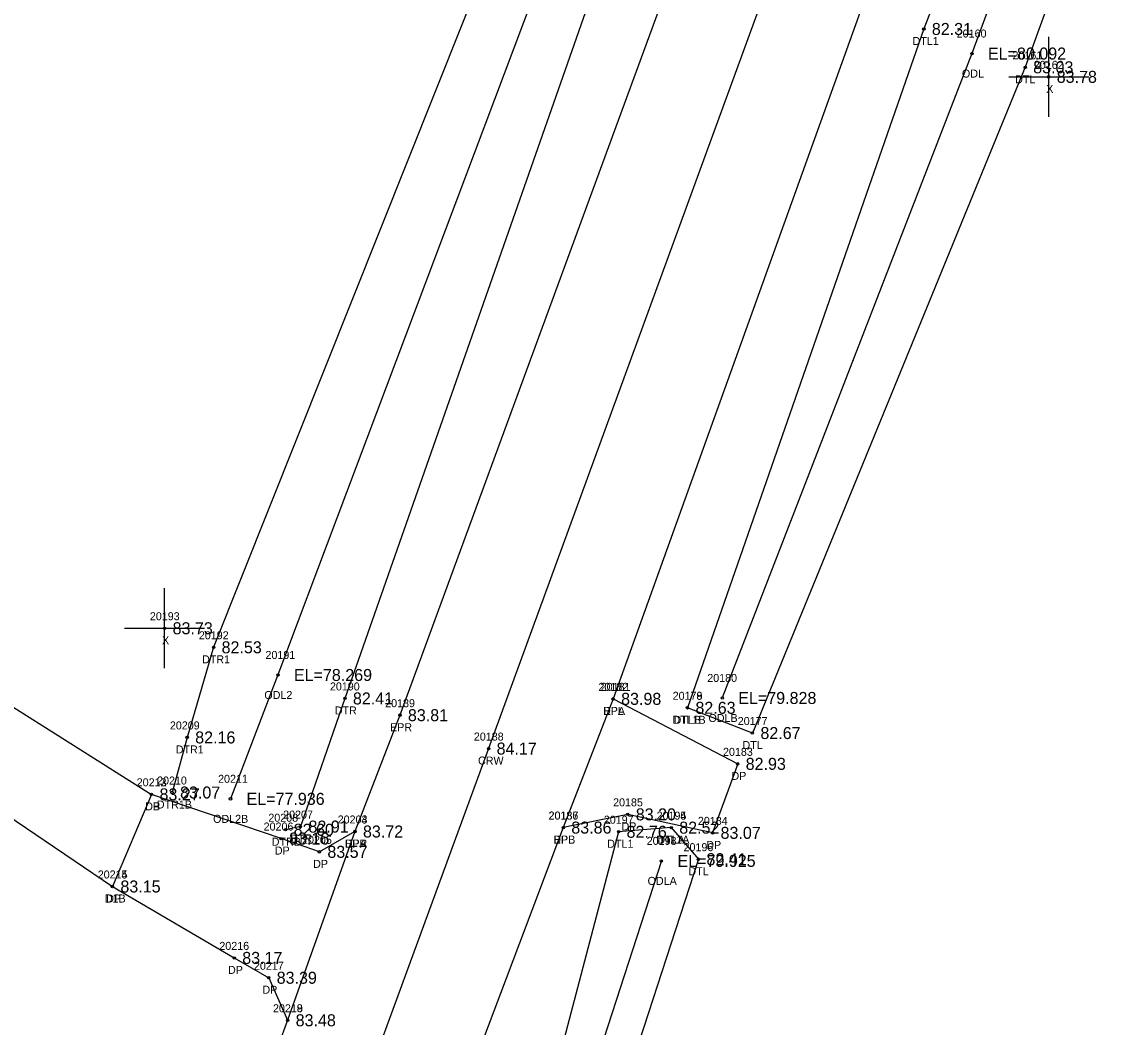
# Model space of a CAD drawing. Extents: x 2140110 to 2141565, y 506241 to 510327.
# Drawn here: x 2141166.2 to 2141303, y 509748.5 to 509874.1 of the extents above; entities that cross this region are included whole.
import ezdxf

# ---------------------------------------------------------------- set-up
doc = ezdxf.new("R2010")
doc.units = 0
for name, color, linetype in [('RD_DTM_BkLn1', 7, 'Continuous'), ('RD_EX_Driveway', 7, 'Continuous'), ('RD_EX_Driveway_txCode', 7, 'Continuous'), ('RD_EX_H2O', 7, 'Continuous'), ('RD_EX_H2O_txCode', 7, 'Continuous'), ('RD_EX_Misc', 7, 'Continuous'), ('RD_EX_Misc_txCode', 7, 'Continuous'), ('RD_EX_Road', 7, 'Continuous'), ('RD_EX_Road_txCode', 7, 'Continuous'), ('RD_EX_TX_Driveway_ELEV', 7, 'Continuous'), ('RD_EX_TX_H2O_ELEV', 7, 'Continuous'), ('RD_EX_TX_Misc_ELEV', 7, 'Continuous'), ('RD_EX_TX_Road_ELEV', 7, 'Continuous'), ('RD_HC_Survey_ELEV', 7, 'Continuous'), ('RD_HC_Survey_txCode', 7, 'Continuous'), ('RD_SMD_Locator', 7, 'Continuous')]:
    doc.layers.add(name, color=color, linetype=linetype)

msp = doc.modelspace()

# ---------------------------------------------------------------- linework, layer by layer
at = {"layer": 'RD_DTM_BkLn1'}
msp.add_lwpolyline([(2141401.24, 510292.17), (2141386.62, 510241.55), (2141370.29, 510189.18), (2141352.34, 510135.64), (2141334.07, 510083.82), (2141314.82, 510031.25), (2141297.4, 509983.45), (2141260.01, 509880.66), (2141224.45, 509783.3), (2141187.1, 509681.41), (2141150.45, 509581.24), (2141112.96, 509478.26), (2141074.89, 509374.78), (2141038.89, 509276.46), (2141003.79, 509180.59), (2140969.89, 509087.8), (2140962.46, 509066.85), (2140921.91, 508956.12), (2140885.66, 508857.72), (2140850.55, 508762.05)], dxfattribs=at)
at = {"layer": 'RD_EX_Driveway'}
for p, q in [((2141078.27, 509843.32), (2141182.34, 509777.58)), ((2141073.6, 509836.63), (2141177.46, 509766.07))]:
    msp.add_line(p, q, dxfattribs=at)
for points in [[(2141240, 509789.51), (2141255.56, 509781.39), (2141252.42, 509772.77), (2141241.83, 509775.08), (2141233.78, 509773.43)], [(2141207.76, 509772.94), (2141203.31, 509770.4), (2141198.53, 509772.06), (2141182.34, 509777.58), (2141177.46, 509766.07), (2141192.68, 509757.15), (2141196.98, 509754.67), (2141199.35, 509749.36)]]:
    msp.add_lwpolyline(points, dxfattribs=at)
at = {"layer": 'RD_EX_H2O'}
msp.add_line((2141246.04, 509769.27), (2141235.76, 509737.67), dxfattribs=at)
for points in [[(2141358.84, 510073.73), (2141351.95, 510067.82), (2141335.19, 510023.26), (2141318.11, 509975.22), (2141278.81, 509873.19), (2141249.28, 509788.39)], [(2141358.84, 510073.73), (2141359.89, 510066.73), (2141343.93, 510018.93), (2141329.02, 509971.91), (2141291.47, 509868.4), (2141257.4, 509785.24), (2141249.28, 509788.39)], [(2141358.84, 510073.73), (2141356.54, 510067.26), (2141339.37, 510020.6), (2141322.95, 509973.6), (2141284.82, 509870.12), (2141253.63, 509789.62)], [(2141264.54, 509972.13), (2141256.83, 509970.45), (2141228.17, 509891.5), (2141190.1, 509795.95), (2141186.8, 509784.69), (2141184.91, 509777.81)], [(2141264.54, 509972.13), (2141269.57, 509963.97), (2141240.79, 509887.5), (2141206.5, 509789.56), (2141200.95, 509773.55), (2141199.1, 509773.16)], [(2141261.59, 509965.87), (2141234.98, 509890.42), (2141198.13, 509792.49), (2141192.21, 509777.02)], [(2141247.26, 509773.42), (2141240.68, 509772.91), (2141231.53, 509738.06), (2141231.2, 509735.67), (2141238.23, 509732.83), (2141239.8, 509736.07)], [(2141247.26, 509773.42), (2141250.66, 509769.48), (2141239.8, 509736.07)]]:
    msp.add_lwpolyline(points, dxfattribs=at)
at = {"layer": 'RD_EX_Misc'}
for p, q in [((2141294.41, 509862.21), (2141294.41, 509872.21)), ((2141289.41, 509867.21), (2141299.41, 509867.21)), ((2141183.98, 509793.33), (2141183.98, 509803.33)), ((2141178.98, 509798.33), (2141188.98, 509798.33))]:
    msp.add_line(p, q, dxfattribs=at)
at = {"layer": 'RD_EX_Road'}
for points in [[(2141389.23, 510293.58), (2141374.66, 510243.58), (2141359.1, 510192.72), (2141341.17, 510140.58), (2141322.74, 510087.97), (2141303.61, 510035.12), (2141287.18, 509990.16), (2141276.99, 509962.02), (2141248.91, 509884.35), (2141213.37, 509787.47), (2141207.76, 509772.94), (2141199.35, 509749.36), (2141191.47, 509727.8), (2141175.93, 509686.04), (2141140.09, 509588.3)], [(2141412.62, 510288.46), (2141398.29, 510238.16), (2141381.65, 510185.39), (2141379.05, 510176.51), (2141367.08, 510141.57), (2141363.58, 510131.95), (2141345.23, 510080.36), (2141326.05, 510027.03), (2141308.64, 509979.4), (2141271.24, 509876.37), (2141240, 509789.51), (2141233.78, 509773.43), (2141223.56, 509746.41), (2141212.18, 509714.93), (2141204.36, 509694.36), (2141197.99, 509676.56), (2141193.66, 509664.6)]]:
    msp.add_lwpolyline(points, dxfattribs=at)
at = {"layer": 'RD_SMD_Locator'}
for centre in [(2141278.81, 509873.19), (2141284.82, 509870.12), (2141291.47, 509868.4), (2141294.41, 509867.21), (2141183.98, 509798.33), (2141190.1, 509795.95), (2141198.13, 509792.49), (2141206.5, 509789.56), (2141240, 509789.51), (2141240, 509789.51), (2141249.28, 509788.39), (2141249.28, 509788.39), (2141253.63, 509789.62), (2141213.37, 509787.47), (2141186.8, 509784.69), (2141257.4, 509785.24), (2141224.45, 509783.3), (2141255.56, 509781.39), (2141182.34, 509777.58), (2141182.34, 509777.58), (2141184.91, 509777.81), (2141192.21, 509777.02), (2141241.83, 509775.08), (2141200.95, 509773.55), (2141233.78, 509773.43), (2141233.78, 509773.43), (2141247.26, 509773.42), (2141247.26, 509773.42), (2141198.53, 509772.06), (2141199.1, 509773.16), (2141207.76, 509772.94), (2141207.76, 509772.94), (2141240.68, 509772.91), (2141252.42, 509772.77), (2141203.31, 509770.4), (2141246.04, 509769.27), (2141250.66, 509769.48), (2141177.46, 509766.07), (2141177.46, 509766.07), (2141192.68, 509757.15), (2141196.98, 509754.67), (2141199.35, 509749.36), (2141199.35, 509749.36)]:
    msp.add_circle(centre, 0.15, dxfattribs=at)

# ---------------------------------------------------------------- texts
at = {"layer": 'RD_EX_Driveway_txCode'}
for s, p in [('20182', (2141238.17, 509790.51)), ('DPA', (2141238.74, 509787.51)), ('20183', (2141253.73, 509782.39)), ('DP', (2141254.78, 509779.39)), ('20212', (2141180.5, 509778.58)), ('20213', (2141180.5, 509778.58)), ('DP', (2141181.56, 509775.58)), ('DB', (2141181.56, 509775.58)), ('20185', (2141240, 509776.08)), ('20204', (2141205.6, 509773.94)), ('20187', (2141231.95, 509774.43)), ('20206', (2141196.35, 509773.06)), ('DP', (2141241.05, 509773.08)), ('20184', (2141250.59, 509773.77)), ('20205', (2141201.15, 509771.4)), ('DPB', (2141232.53, 509771.43)), ('DP', (2141197.75, 509770.06)), ('DPA', (2141206.49, 509770.94)), ('DP', (2141251.64, 509770.77)), ('DP', (2141202.53, 509768.4)), ('20214', (2141175.63, 509767.07)), ('20215', (2141175.63, 509767.07)), ('D1B', (2141176.52, 509764.07)), ('DP', (2141176.68, 509764.07)), ('20216', (2141190.82, 509758.15)), ('DP', (2141191.9, 509755.15)), ('20217', (2141195.14, 509755.67)), ('DP', (2141196.2, 509752.67)), ('20218', (2141197.52, 509750.36))]:
    msp.add_text(s, height=1, dxfattribs=at).set_placement(p)
at = {"layer": 'RD_EX_H2O_txCode'}
for s, p in [('DTL1', (2141277.4, 509871.19)), ('20160', (2141282.92, 509872.12)), ('20161', (2141289.89, 509869.4)), ('ODL', (2141283.57, 509867.12)), ('DTL', (2141290.22, 509866.4)), ('20192', (2141188.26, 509796.95)), ('20191', (2141196.58, 509794.49)), ('DTR1', (2141188.66, 509793.95)), ('20180', (2141251.76, 509791.62)), ('20190', (2141204.63, 509790.56)), ('ODL2', (2141196.44, 509789.49)), ('20178', (2141247.44, 509789.39)), ('20179', (2141247.44, 509789.39)), ('DTR', (2141205.23, 509787.56)), ('DTL1B', (2141247.4, 509786.39)), ('DTLB', (2141247.56, 509786.39)), ('ODLB', (2141251.91, 509786.62)), ('20177', (2141255.57, 509786.24)), ('20209', (2141184.64, 509785.69)), ('DTR1', (2141185.37, 509782.69)), ('DTL', (2141256.16, 509783.24)), ('20210', (2141183.04, 509778.81)), ('20211', (2141190.66, 509779.02)), ('DTR1B', (2141183.01, 509775.81)), ('ODL2B', (2141190.04, 509774.02)), ('20208', (2141196.94, 509774.16)), ('20207', (2141198.79, 509774.55)), ('20197', (2141238.84, 509773.91)), ('20194', (2141245.43, 509774.42)), ('20195', (2141245.43, 509774.42)), ('DTRB', (2141197.36, 509771.16)), ('DTR', (2141199.68, 509771.55)), ('20198', (2141244.2, 509771.27)), ('DTL1A', (2141245.37, 509771.42)), ('DTLA', (2141245.53, 509771.42)), ('DTL1', (2141239.27, 509770.91)), ('20196', (2141248.8, 509770.48)), ('DTL', (2141249.41, 509767.48)), ('ODLA', (2141244.31, 509766.27))]:
    msp.add_text(s, height=1, dxfattribs=at).set_placement(p)
at = {"layer": 'RD_EX_Misc_txCode'}
for s, p in [('20162', (2141292.55, 509868.21)), ('X', (2141294.1, 509865.21)), ('20193', (2141182.14, 509799.33)), ('X', (2141183.66, 509796.33))]:
    msp.add_text(s, height=1, dxfattribs=at).set_placement(p)
at = {"layer": 'RD_EX_Road_txCode'}
for s, p in [('20181', (2141238.45, 509790.51)), ('20189', (2141211.53, 509788.47)), ('EPL', (2141238.8, 509787.51)), ('EPR', (2141212.14, 509785.47)), ('20203', (2141205.6, 509773.94)), ('20186', (2141231.93, 509774.43)), ('EPL', (2141232.58, 509771.43)), ('EPR', (2141206.53, 509770.94)), ('20219', (2141197.52, 509750.36))]:
    msp.add_text(s, height=1, dxfattribs=at).set_placement(p)
at = {"layer": 'RD_EX_TX_Driveway_ELEV'}
for s, p in [('83.98', (2141241, 509788.76)), ('82.93', (2141256.56, 509780.64)), ('83.27', (2141183.34, 509776.83)), ('83.27', (2141183.34, 509776.83)), ('83.20', (2141242.83, 509774.33)), ('83.72', (2141208.76, 509772.19)), ('83.86', (2141234.78, 509772.68)), ('83.07', (2141253.42, 509772.02)), ('83.16', (2141199.53, 509771.31)), ('83.57', (2141204.31, 509769.65)), ('83.15', (2141178.46, 509765.32)), ('83.15', (2141178.46, 509765.32)), ('83.17', (2141193.68, 509756.4)), ('83.39', (2141197.98, 509753.92)), ('83.48', (2141200.35, 509748.61))]:
    msp.add_text(s, height=1.5, dxfattribs=at).set_placement(p)
at = {"layer": 'RD_EX_TX_H2O_ELEV'}
for s, p in [('82.31', (2141279.81, 509872.44)), ('EL=80.092', (2141286.82, 509869.37)), ('83.03', (2141292.47, 509867.65)), ('82.53', (2141191.1, 509795.2)), ('EL=78.269', (2141200.13, 509791.74)), ('82.41', (2141207.5, 509788.81)), ('EL=79.828', (2141255.63, 509788.87)), ('82.63', (2141250.28, 509787.64)), ('82.63', (2141250.28, 509787.64)), ('82.67', (2141258.4, 509784.49)), ('82.16', (2141187.8, 509783.94)), ('83.07', (2141185.91, 509777.06)), ('EL=77.936', (2141194.21, 509776.27)), ('82.60', (2141200.1, 509772.41)), ('82.91', (2141201.95, 509772.8)), ('82.76', (2141241.68, 509772.16)), ('82.52', (2141248.26, 509772.67)), ('82.52', (2141248.26, 509772.67)), ('EL=79.925', (2141248.04, 509768.52)), ('82.41', (2141251.66, 509768.73))]:
    msp.add_text(s, height=1.5, dxfattribs=at).set_placement(p)
at = {"layer": 'RD_EX_TX_Misc_ELEV'}
for s, p in [('83.78', (2141295.41, 509866.46)), ('83.73', (2141184.98, 509797.58))]:
    msp.add_text(s, height=1.5, dxfattribs=at).set_placement(p)
at = {"layer": 'RD_EX_TX_Road_ELEV'}
for s, p in [('83.98', (2141241, 509788.76)), ('83.81', (2141214.37, 509786.72)), ('83.72', (2141208.76, 509772.19)), ('83.86', (2141234.78, 509772.68)), ('83.48', (2141200.35, 509748.61))]:
    msp.add_text(s, height=1.5, dxfattribs=at).set_placement(p)
at = {"layer": 'RD_HC_Survey_ELEV'}
msp.add_text('84.17', height=1.5, dxfattribs=at).set_placement((2141225.45, 509782.55))
at = {"layer": 'RD_HC_Survey_txCode'}
for s, p in [('20188', (2141222.61, 509784.3)), ('CRW', (2141223.13, 509781.3))]:
    msp.add_text(s, height=1, dxfattribs=at).set_placement(p)

doc.saveas('drawing.dxf')
